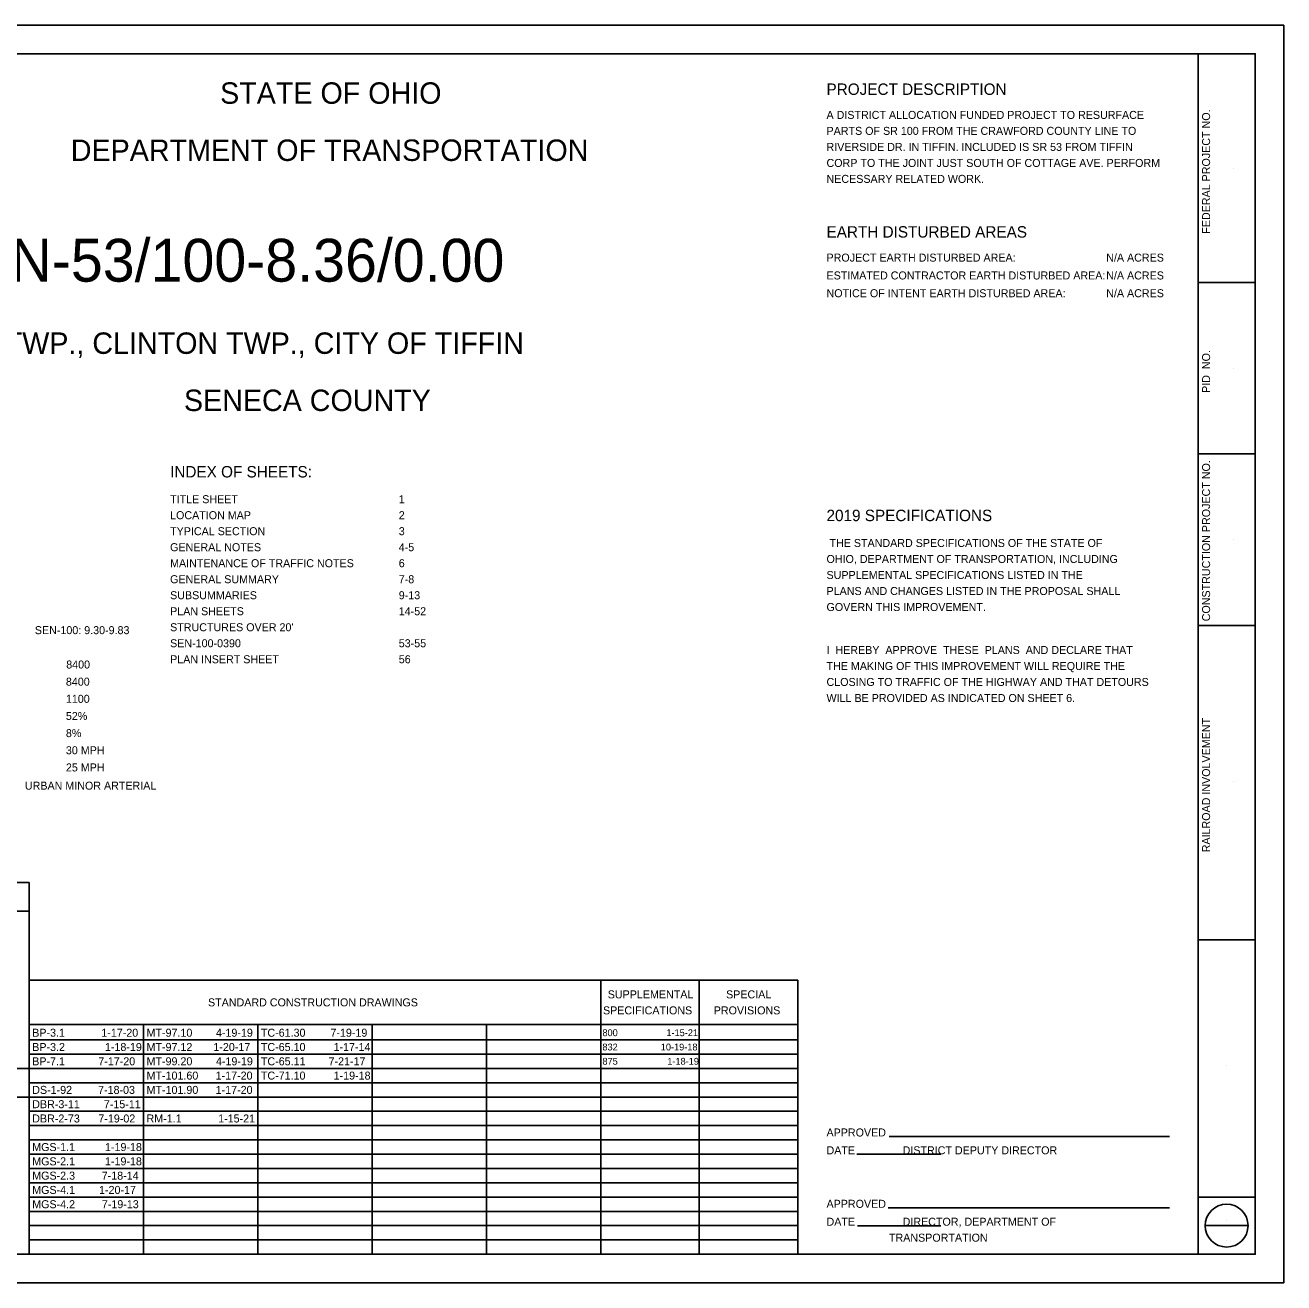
# Model space of a CAD drawing. Extents: x 0 to 34, y 0 to 22.
# Drawn here: x 11.98 to 34, y 0 to 22 of the extents above; entities that cross this region are included whole.
import ezdxf

# ---------------------------------------------------------------- set-up
doc = ezdxf.new("R2010")
doc.units = 0
for name, color, linetype in [('SH_Border', 7, 'Continuous'), ('SH_Cut_Line', 7, 'Continuous'), ('SH_Data', 7, 'Continuous'), ('SH_Text', 7, 'Continuous')]:
    doc.layers.add(name, color=color, linetype=linetype)

msp = doc.modelspace()

# ---------------------------------------------------------------- linework, layer by layer
at = {"layer": 'SH_Border'}
for p, q in [((32.5, 0.5), (32.5, 21.5)), ((32.5, 17.5), (33.5, 17.5)), ((32.5, 14.5), (33.5, 14.5)), ((32.5, 11.5), (33.5, 11.5)), ((32.5, 6), (33.5, 6)), ((32.5, 1.5), (33.5, 1.5))]:
    msp.add_line(p, q, dxfattribs=at)
msp.add_lwpolyline([(2, 21.5), (33.5, 21.5), (33.5, 0.5), (2, 0.5)], close=True, dxfattribs=at)
at = {"layer": 'SH_Cut_Line'}
msp.add_lwpolyline([(0, 0), (34, 0), (34, 22), (0, 22)], close=True, dxfattribs=at)
at = {"layer": 'SH_Data'}
for p, q in [((33.125, 19.5), (33.125, 19.5)), ((33.125, 16), (33.125, 16)), ((33.125, 13), (33.125, 13)), ((26, 11.14), (26, 11.14)), ((26, 11.14), (26, 11.14)), ((33.125, 8.766), (33.125, 8.766)), ((9.25, 7), (12.05, 7)), ((12.05, 0.5), (12.05, 7)), ((9.25, 6.5), (12.05, 6.5)), ((12.05, 5.292), (25.5, 5.292)), ((22.05, 0.5), (22.05, 5.292)), ((23.775, 0.5), (23.775, 5.292)), ((25.5, 0.5), (25.5, 5.292)), ((12.05, 4.521), (25.5, 4.521)), ((14.05, 0.5), (14.05, 4.521)), ((16.05, 0.5), (16.05, 4.521)), ((18.05, 0.5), (18.05, 4.521)), ((20.05, 0.5), (20.05, 4.521)), ((12.05, 4.25), (25.5, 4.25)), ((12.05, 4), (25.5, 4)), ((9.25, 3.75), (12.05, 3.75)), ((12.05, 3.75), (25.5, 3.75)), ((33, 3.799), (33, 3.799)), ((12.05, 3.5), (25.5, 3.5)), ((9.25, 3.25), (12.05, 3.25)), ((12.05, 3.25), (25.5, 3.25)), ((12.05, 3), (25.5, 3)), ((12.05, 2.75), (25.5, 2.75)), ((12.05, 2.5), (25.5, 2.5)), ((27.095, 2.56), (32, 2.56)), ((12.05, 2.25), (25.5, 2.25)), ((26.533, 2.248), (28, 2.248)), ((12.05, 2), (25.5, 2)), ((12.05, 1.75), (25.5, 1.75)), ((12.05, 1.5), (25.5, 1.5)), ((12.05, 1.25), (25.5, 1.25)), ((27.08, 1.312), (32, 1.312)), ((12.05, 1), (25.5, 1)), ((26.542, 0.999), (28, 0.999)), ((32.625, 1), (33.375, 1)), ((33, 1.085), (33, 1.085)), ((12.05, 0.75), (25.5, 0.75)), ((33, 0.745), (33, 0.745))]:
    msp.add_line(p, q, dxfattribs=at)
msp.add_circle((33, 1), 0.375, dxfattribs=at)

# ---------------------------------------------------------------- texts
for s, height, p in [('STATE OF OHIO', 0.375, (15.392, 20.625)), ('PROJECT DESCRIPTION', 0.2, (26, 20.78)), ('A DISTRICT ALLOCATION FUNDED PROJECT TO RESURFACE', 0.14, (26, 20.36)), ('PARTS OF SR 100 FROM THE CRAWFORD COUNTY LINE TO', 0.14, (26, 20.081)), ('DEPARTMENT OF TRANSPORTATION', 0.375, (12.78, 19.625)), ('RIVERSIDE DR. IN TIFFIN. INCLUDED IS SR 53 FROM TIFFIN', 0.14, (26, 19.8)), ('CORP TO THE JOINT JUST SOUTH OF COTTAGE AVE. PERFORM', 0.14, (26, 19.52)), ('NECESSARY RELATED WORK.', 0.14, (26, 19.241)), ('SEN-53/100-8.36/0.00', 0.75, (10.385, 17.513)), ('EARTH DISTURBED AREAS', 0.2, (26, 18.284)), ('PROJECT EARTH DISTURBED AREA:', 0.14, (26, 17.864)), ('N/A ACRES', 0.14, (30.893, 17.864)), ('ESTIMATED CONTRACTOR EARTH DISTURBED AREA:', 0.14, (26, 17.552)), ('N/A ACRES', 0.14, (30.893, 17.552)), ('NOTICE OF INTENT EARTH DISTURBED AREA:', 0.14, (26, 17.241)), ('N/A ACRES', 0.14, (30.893, 17.241)), ('EDEN TWP., CLINTON TWP., CITY OF TIFFIN', 0.375, (10.092, 16.25)), ('SENECA COUNTY', 0.375, (14.759, 15.25)), ('INDEX OF SHEETS:', 0.2, (14.517, 14.088)), ('TITLE SHEET', 0.14, (14.517, 13.638)), ('1', 0.14, (18.517, 13.638)), ('LOCATION MAP', 0.14, (14.517, 13.358)), ('2', 0.14, (18.517, 13.358)), ('2019 SPECIFICATIONS', 0.2, (26, 13.324)), ('TYPICAL SECTION', 0.14, (14.517, 13.078)), ('3', 0.14, (18.517, 13.078)), (' THE STANDARD SPECIFICATIONS OF THE STATE OF', 0.14, (26, 12.872)), ('GENERAL NOTES', 0.14, (14.517, 12.798)), ('4-5', 0.14, (18.517, 12.798)), ('MAINTENANCE OF TRAFFIC NOTES', 0.14, (14.517, 12.518)), ('6', 0.14, (18.517, 12.518)), ('OHIO, DEPARTMENT OF TRANSPORTATION, INCLUDING', 0.14, (26, 12.592)), ('GENERAL SUMMARY', 0.14, (14.517, 12.238)), ('7-8', 0.14, (18.517, 12.238)), ('SUPPLEMENTAL SPECIFICATIONS LISTED IN THE', 0.14, (26, 12.312)), ('PLANS AND CHANGES LISTED IN THE PROPOSAL SHALL', 0.14, (26, 12.032)), ('SUBSUMMARIES', 0.14, (14.517, 11.958)), ('9-13', 0.14, (18.517, 11.958)), ('GOVERN THIS IMPROVEMENT.', 0.14, (26, 11.752)), ('PLAN SHEETS', 0.14, (14.517, 11.678)), ('14-52', 0.14, (18.517, 11.678)), ("STRUCTURES OVER 20'", 0.14, (14.517, 11.398)), ('SEN-100-0390', 0.14, (14.517, 11.118)), ('53-55', 0.14, (18.517, 11.118)), ('8400', 0.14, (12.7, 10.746)), ('PLAN INSERT SHEET', 0.14, (14.517, 10.838)), ('56', 0.14, (18.517, 10.838)), ('8400', 0.14, (12.694, 10.446)), ('1100', 0.14, (12.694, 10.146)), ('52%', 0.14, (12.694, 9.846)), ('8%', 0.14, (12.694, 9.546)), ('30 MPH', 0.14, (12.694, 9.246)), ('25 MPH', 0.14, (12.694, 8.946)), ('URBAN MINOR ARTERIAL', 0.14, (11.977, 8.627)), ('SUPPLEMENTAL', 0.14, (22.173, 4.976)), ('SPECIAL', 0.14, (24.243, 4.976)), ('STANDARD CONSTRUCTION DRAWINGS', 0.14, (15.18, 4.836)), ('SPECIFICATIONS', 0.14, (22.09, 4.696)), ('PROVISIONS', 0.14, (24.027, 4.696)), ('BP-3.1', 0.14, (12.105, 4.305)), ('1-17-20', 0.14, (13.314, 4.305)), ('MT-97.10', 0.14, (14.105, 4.305)), ('4-19-19', 0.14, (15.319, 4.305)), ('TC-61.30', 0.14, (16.105, 4.305)), ('7-19-19', 0.14, (17.322, 4.305)), ('800', 0.12, (22.08, 4.315)), ('1-15-21', 0.12, (23.199, 4.315)), ('BP-3.2', 0.14, (12.105, 4.055)), ('1-18-19', 0.14, (13.377, 4.055)), ('MT-97.12', 0.14, (14.105, 4.055)), ('1-20-17', 0.14, (15.274, 4.055)), ('TC-65.10', 0.14, (16.105, 4.055)), ('1-17-14', 0.14, (17.376, 4.055)), ('832', 0.12, (22.08, 4.065)), ('10-19-18', 0.12, (23.101, 4.065)), ('BP-7.1', 0.14, (12.105, 3.805)), ('7-17-20', 0.14, (13.261, 3.805)), ('MT-99.20', 0.14, (14.105, 3.805)), ('4-19-19', 0.14, (15.319, 3.805)), ('TC-65.11', 0.14, (16.105, 3.805)), ('7-21-17', 0.14, (17.289, 3.805)), ('875', 0.12, (22.08, 3.815)), ('1-18-19', 0.12, (23.215, 3.815)), ('MT-101.60', 0.14, (14.105, 3.555)), ('1-17-20', 0.14, (15.314, 3.555)), ('TC-71.10', 0.14, (16.105, 3.555)), ('1-19-18', 0.14, (17.378, 3.555)), ('DS-1-92', 0.14, (12.105, 3.305)), ('7-18-03', 0.14, (13.257, 3.305)), ('MT-101.90', 0.14, (14.105, 3.305)), ('1-17-20', 0.14, (15.314, 3.305)), ('DBR-3-11', 0.14, (12.105, 3.055)), ('7-15-11', 0.14, (13.358, 3.055)), ('DBR-2-73', 0.14, (12.105, 2.805)), ('7-19-02', 0.14, (13.262, 2.805)), ('RM-1.1', 0.14, (14.105, 2.805)), ('1-15-21', 0.14, (15.358, 2.805)), ('APPROVED', 0.14, (26, 2.56)), ('MGS-1.1', 0.14, (12.105, 2.305)), ('1-19-18', 0.14, (13.378, 2.305)), ('DATE                DISTRICT DEPUTY DIRECTOR', 0.14, (26, 2.248)), ('MGS-2.1', 0.14, (12.105, 2.055)), ('1-19-18', 0.14, (13.378, 2.055)), ('MGS-2.3', 0.14, (12.105, 1.805)), ('7-18-14', 0.14, (13.321, 1.805)), ('MGS-4.1', 0.14, (12.105, 1.555)), ('1-20-17', 0.14, (13.274, 1.555)), ('MGS-4.2', 0.14, (12.105, 1.305)), ('7-19-13', 0.14, (13.323, 1.305)), ('APPROVED', 0.14, (26, 1.312)), ('DATE                DIRECTOR, DEPARTMENT OF', 0.14, (26, 0.999)), ('                     TRANSPORTATION', 0.14, (26, 0.72))]:
    msp.add_text(s, height=height, dxfattribs=at).set_placement(p)
for s, p in [('FEDERAL PROJECT NO.', (32.71, 18.352)), ('PID  NO.', (32.71, 15.567)), ('CONSTRUCTION PROJECT NO.', (32.71, 11.572)), ('RAILROAD INVOLVEMENT', (32.71, 7.531))]:
    msp.add_text(s, height=0.14, rotation=90, dxfattribs=at).set_placement(p)
at = {"layer": 'SH_Text'}
for s, p in [('SEN-100: 9.30-9.83', (12.151, 11.347)), ('I  HEREBY  APPROVE  THESE  PLANS  AND DECLARE THAT', (26, 11)), ('THE MAKING OF THIS IMPROVEMENT WILL REQUIRE THE', (26, 10.72)), ('CLOSING TO TRAFFIC OF THE HIGHWAY AND THAT DETOURS', (26, 10.441)), ('WILL BE PROVIDED AS INDICATED ON SHEET 6.', (26, 10.16))]:
    msp.add_text(s, height=0.14, dxfattribs=at).set_placement(p)

doc.saveas('drawing.dxf')
